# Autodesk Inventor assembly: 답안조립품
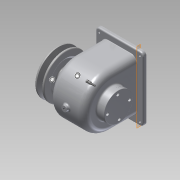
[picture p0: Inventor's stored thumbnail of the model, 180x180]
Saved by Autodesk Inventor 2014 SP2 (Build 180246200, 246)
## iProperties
Created: 2016-01
Part Number: 답안조립품
Document SubType Name: Assembly
Designer: Administrator
Author: Administrator
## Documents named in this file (16)
- C:\Users\Administrator\Desktop\460105V1001\답안조립품.iam
- C:\Users\Administrator\Desktop\460105V1001\V-벨트풀리.ipt
- C:\Users\Administrator\Desktop\460105V1001\뒤커버.ipt
- C:\Users\Administrator\Desktop\460105V1001\멈춤나사 - M4x10.ipt
- C:\Users\Administrator\Desktop\460105V1001\베어링 6203.ipt
- C:\Users\Administrator\Desktop\460105V1001\본체.ipt
- C:\Users\Administrator\Desktop\460105V1001\볼트 M3 x 8.ipt
- C:\Users\Administrator\Desktop\460105V1001\볼트 M3 x 10.ipt
- C:\Users\Administrator\Desktop\460105V1001\부시1.ipt
- C:\Users\Administrator\Desktop\460105V1001\부시2.ipt
- C:\Users\Administrator\Desktop\460105V1001\스퍼기어.ipt
- C:\Users\Administrator\Desktop\460105V1001\앞커버.ipt
- C:\Users\Administrator\Desktop\460105V1001\오일씰 28 40 8.ipt
- C:\Users\Administrator\Desktop\460105V1001\축.ipt
- C:\Users\Administrator\Desktop\460105V1001\키 - 5 x 5 x 18.ipt
- C:\Users\Administrator\Desktop\460105V1001\키 - 6 x 6 x 22.ipt
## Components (3 placed, 3 different names)
1. V-벨트풀리:1
2. ISO 4762 M3 x 8:1
3. ISO 4762 M3 x 10:1
